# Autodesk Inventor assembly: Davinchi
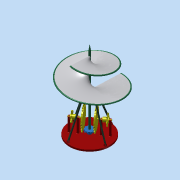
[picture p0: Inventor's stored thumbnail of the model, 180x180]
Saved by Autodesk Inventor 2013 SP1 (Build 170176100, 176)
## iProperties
Created: 2016-04
Part Number: Davinchi
Document SubType Name: Assembly
Designer: Кравец
Author: Кравец
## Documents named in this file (8)
- D:\Кравец\Тимчасова\Новая папка\Davinchi.iam
- D:\Кравец\Тимчасова\Новая папка\Vint.ipt
- D:\Кравец\Тимчасова\Новая папка\det2.ipt
- D:\Кравец\Тимчасова\Новая папка\de3.ipt
- D:\Кравец\Тимчасова\Новая папка\det4.ipt
- D:\Кравец\Тимчасова\Новая папка\det5.ipt
- D:\Кравец\Тимчасова\Новая папка\det6.ipt
- D:\Кравец\Тимчасова\Новая папка\det7.ipt
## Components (11 placed, 7 different names)
1. Vint:1 — Совмещение:1, Вставка:1, Совмещение:3, Совмещение:8, Совмещение:9, Вставка:6
2. det2:1 — Совмещение:1, Заподлицо:1, Вставка:2, Вставка:3, Вставка:4, Вставка:5
3. de3:1 — Вставка:1
4. det4:1 — Совмещение:3, Заподлицо:1, Совмещение:4, Совмещение:5, Совмещение:6, Совмещение:7, Совмещение:8, Вставка:7, Вставка:8
5. det5:1 — Вставка:2, Совмещение:4
6. det5:2 — Вставка:3, Совмещение:5
7. det5:3 — Вставка:4, Совмещение:7
8. det5:4 — Вставка:5, Совмещение:6
9. det6:1 — Совмещение:9, Вставка:6
10. det7:1 — Вставка:7
11. det7:2 — Вставка:8
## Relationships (17: Mate 8, Insert 8, Flush 1)
- Совмещение:1 [Mate]: Vint:1 ↔ det2:1
- Вставка:1 [Insert]: Vint:1 ↔ de3:1
- Совмещение:3 [Mate]: Vint:1 ↔ det4:1
- Заподлицо:1 [Flush]: det2:1 ↔ det4:1
- Вставка:2 [Insert]: det2:1 ↔ det5:1
- Совмещение:4 [Mate]: det4:1 ↔ det5:1
- Вставка:3 [Insert]: det2:1 ↔ det5:2
- Вставка:4 [Insert]: det2:1 ↔ det5:3
- Вставка:5 [Insert]: det2:1 ↔ det5:4
- Совмещение:5 [Mate]: det4:1 ↔ det5:2
- Совмещение:6 [Mate]: det4:1 ↔ det5:4
- Совмещение:7 [Mate]: det4:1 ↔ det5:3
- Совмещение:8 [Mate]: Vint:1 ↔ det4:1
- Совмещение:9 [Mate]: Vint:1 ↔ det6:1
- Вставка:6 [Insert]: Vint:1 ↔ det6:1
- Вставка:7 [Insert]: det4:1 ↔ det7:1
- Вставка:8 [Insert]: det4:1 ↔ det7:2
